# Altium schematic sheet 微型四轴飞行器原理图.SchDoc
size A4
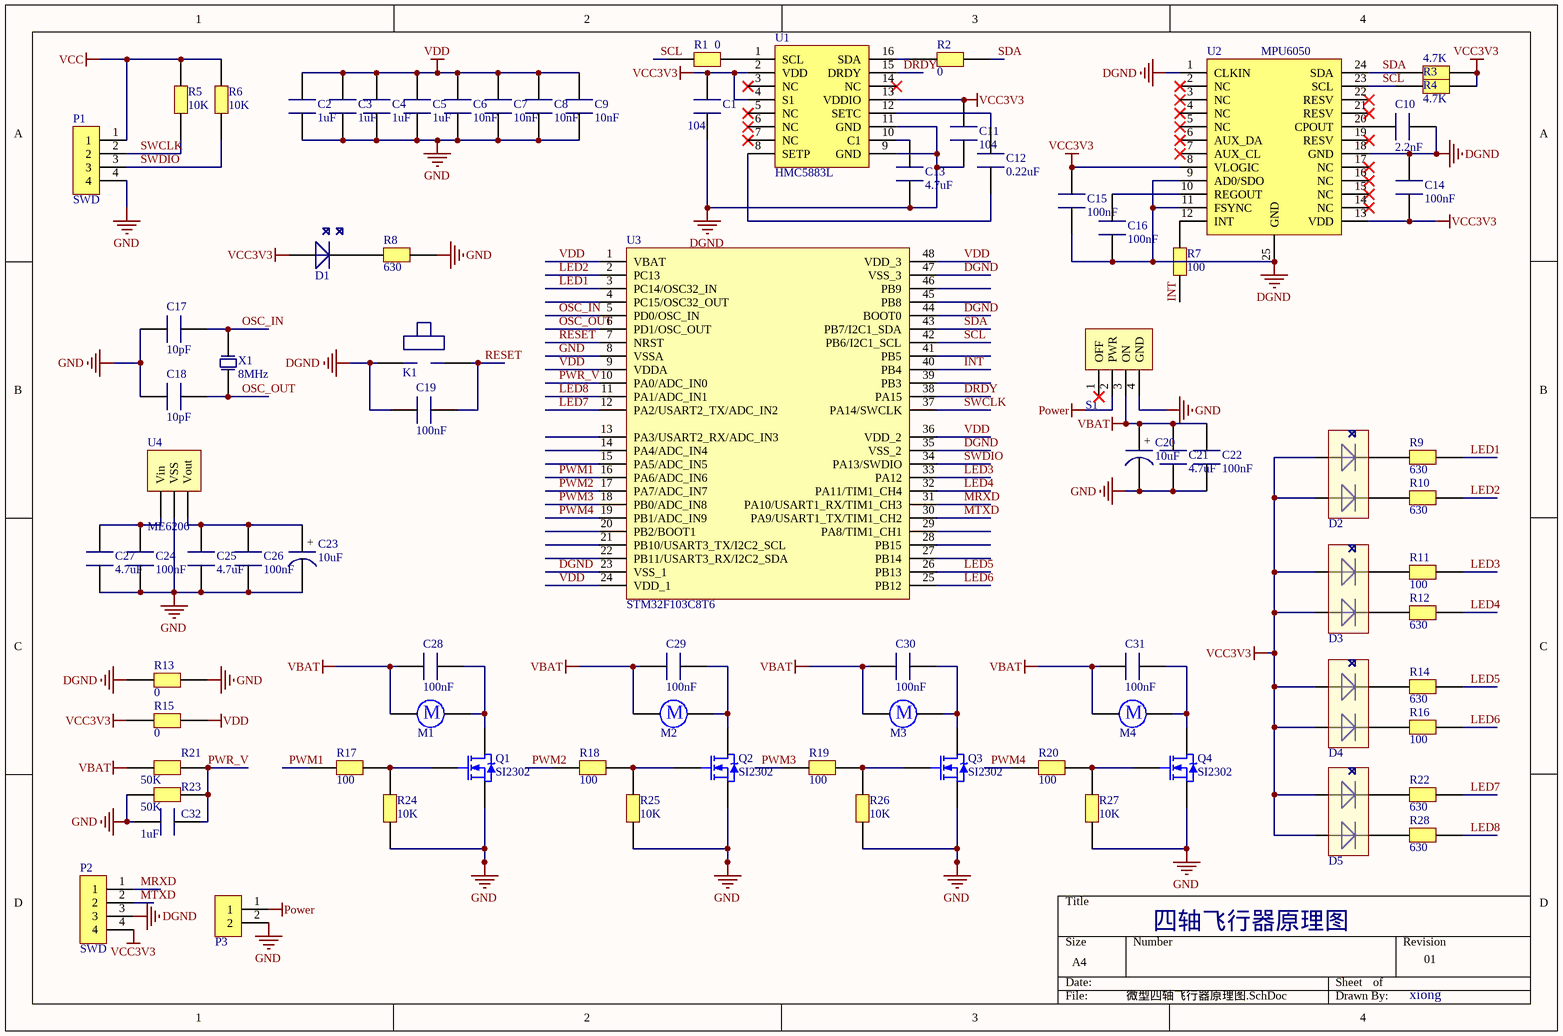
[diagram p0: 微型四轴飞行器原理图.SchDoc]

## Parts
C1  104  [C0603]
C2  ֵ: 1uF  [C0603]  (hidden comment: 104)
C3  ֵ: 1uF  [C0603]  (hidden comment: 104)
C4  ֵ: 1uF  [C0603]  (hidden comment: 104)
C5  ֵ: 1uF  [C0603]  (hidden comment: 104)
C6  ֵ: 10nF  [C0603]  (hidden comment: 104)
C7  ֵ: 10nF  [C0603]  (hidden comment: 104)
C8  ֵ: 10nF  [C0603]  (hidden comment: 104)
C9  ֵ: 10nF  [C0603]  (hidden comment: 104)
C10  ֵ: 2.2nF  [C0603]  (hidden comment: 104)
C11  104  [C0603]
C12  ֵ: 0.22uF  [C0603]  (hidden comment: 104)
C13  ֵ: 4.7uF  [C0603]  (hidden comment: 104)
C14  ֵ: 100nF  [C0603]  (hidden comment: 104)
C15  ֵ: 100nF  [C0603]  (hidden comment: 104)
C16  ֵ: 100nF  [C0603]  (hidden comment: 104)
C17  ֵ: 10pF  [C0603]  (hidden comment: 104)
C18  ֵ: 10pF  [C0603]  (hidden comment: 104)
C19  ֵ: 100nF  [C0603]  (hidden comment: 104)
C20  10uF  [TAJ-A1206]
C21  ֵ: 4.7uF  [C0603]  (hidden comment: 104)
C22  ֵ: 100nF  [C0603]  (hidden comment: 104)
C23  10uF  [TAJ-A1206]
C24  ֵ: 100nF  [C0603]  (hidden comment: 104)
C25  ֵ: 4.7uF  [C0603]  (hidden comment: 104)
C26  ֵ: 100nF  [C0603]  (hidden comment: 104)
C27  ֵ: 4.7uF  [C0603]  (hidden comment: 104)
C28  ֵ: 100nF  [C0603]  (hidden comment: 104)
C29  ֵ: 100nF  [C0603]  (hidden comment: 104)
C30  ֵ: 100nF  [C0603]  (hidden comment: 104)
C31  ֵ: 100nF  [C0603]  (hidden comment: 104)
C32  ֵ: 1uF  [C0603]  (hidden comment: 104)
D1  LED  [LED0805]  (value not drawn)
D2  LED2  [LED2]  (value not drawn)
D3  LED2  [LED2]  (value not drawn)
D4  LED2  [LED2]  (value not drawn)
D5  LED2  [LED2]  (value not drawn)
K1  KEY_SOP_2  [KEY_SOP2]  (value not drawn)
M1  Motor720  [Motor720]  (value not drawn)
M2  Motor720  [Motor720]  (value not drawn)
M3  Motor720  [Motor720]  (value not drawn)
M4  Motor720  [Motor720]  (value not drawn)
P1  下载接口: SWD  [PIN-4P]  (hidden comment: PIN-4P)
P2  下载接口: SWD  [PIN-4P]  (hidden comment: PIN-4P)
P3  PIN-2P  [PIN-2P]  (value not drawn)
Q1  SI2302  [SOT-23]
Q2  SI2302  [SOT-23]
Q3  SI2302  [SOT-23]
Q4  SI2302  [SOT-23]
R1  ֵ: 0  [R0603]  (hidden comment: 100)
R2  ֵ: 0  [R0603]  (hidden comment: 100)
R3  ֵ: 4.7K  [R0603]  (hidden comment: 100)
R4  ֵ: 4.7K  [R0603]  (hidden comment: 100)
R5  ֵ: 10K  [R0603]  (hidden comment: 100)
R6  ֵ: 10K  [R0603]  (hidden comment: 100)
R7  100  [R0603]
R8  ֵ: 630  [R0603]  (hidden comment: 100)
R9  ֵ: 630  [R0603]  (hidden comment: 100)
R10  ֵ: 630  [R0603]  (hidden comment: 100)
R11  100  [R0603]
R12  ֵ: 630  [R0603]  (hidden comment: 100)
R13  ֵ: 0  [R0603]  (hidden comment: 100)
R14  ֵ: 630  [R0603]  (hidden comment: 100)
R15  ֵ: 0  [R0603]  (hidden comment: 100)
R16  100  [R0603]
R17  100  [R0603]
R18  100  [R0603]
R19  100  [R0603]
R20  100  [R0603]
R21  50K  [R0603]
R22  ֵ: 630  [R0603]  (hidden comment: 100)
R23  ֵ: 50K  [R0603]  (hidden comment: 100)
R24  ֵ: 10K  [R0603]  (hidden comment: 100)
R25  ֵ: 10K  [R0603]  (hidden comment: 100)
R26  ֵ: 10K  [R0603]  (hidden comment: 100)
R27  ֵ: 10K  [R0603]  (hidden comment: 100)
R28  ֵ: 630  [R0603]  (hidden comment: 100)
S1  SwitchPin7  [SwitchPin7]  (value not drawn)
U1  HMC5883L  [HMC5883L-QFN]
U2  MPU6050  [MPU6050QFN]
U3  STM32F103C8T6  [LQFP48 7X7]
U4  ME6206  [sot-23]
X1  8MHz  [XTAL3_SOP]

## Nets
DGND: C1.1 C10.2 C11.2 C13.1 C14.2 C15.1 C16.1 C19.1 K1.1 P2.3 R13.1 U1.9(GND) U1.11(GND) U2.1(CLKIN) U2.9(AD0/SDO) U2.11(FSYNC) U2.18(GND) U2.25(GND) U3.23(VSS_1) U3.35(VSS_2) U3.44(BOOT0) U3.47(VSS_3)
GND: C2.1 C3.1 C4.1 C5.1 C6.1 C7.1 C8.1 C9.1 C17.1 C18.1 C20.2 C21.1 C22.1 C23.2 C24.1 C25.1 C26.1 C27.1 C32.2 P1.4 P3.2 Q1.2(S) Q2.2(S) Q3.2(S) Q4.2(S) R8.1 R13.2 R23.2 R24.1 R25.1 R26.1 R27.1 S1.4(GND) U3.8(VSSA) U4.1(VSS)
Power: P3.1 S1.2(PWR)
VBAT: C20.1 C21.2 C22.2 C28.1 C29.1 C30.1 C31.1 M1.1 M2.1 M3.1 M4.1 R21.2 S1.3(ON)
VCC: P1.1 R5.2 R6.2
VCC3V3: C1.2 C11.1 C14.1 C15.2 D1.1 D2.1 D2.2 D3.1 D3.2 D4.1 D4.2 D5.1 D5.2 P2.4 R3.1 R4.1 R15.1 U1.2(VDD) U1.4(S1) U1.13(VDDIO) U2.8(VLOGIC) U2.13(VDD)
VDD: C2.2 C3.2 C4.2 C5.2 C6.2 C7.2 C8.2 C9.2 R15.2 U3.1(VBAT) U3.9(VDDA) U3.24(VDD_1) U3.36(VDD_2) U3.48(VDD_3)
DRDY: U1.15(DRDY) U3.38(PA15)
INT: R7.1 U3.40(PB4)
LED1: R9.2 U3.3(PC14/OSC32_IN)
LED2: R10.2 U3.2(PC13)
LED3: R11.2 U3.33(PA12)
LED4: R12.2 U3.32(PA11/TIM1_CH4)
LED5: R14.2 U3.26(PB13)
LED6: R16.2 U3.25(PB12)
LED7: R22.2 U3.12(PA2/USART2_TX/ADC_IN2)
LED8: R28.2 U3.11(PA1/ADC_IN1)
MRXD: P2.1 U3.31(PA10/USART1_RX/TIM1_CH3)
MTXD: P2.2 U3.30(PA9/USART1_TX/TIM1_CH2)
OSC_IN: C17.2 U3.5(PD0/OSC_IN) X1.2
OSC_OUT: C18.2 U3.6(PD1/OSC_OUT) X1.1
PWM1: R17.2 U3.16(PA6/ADC_IN6)
PWM2: R18.2 U3.17(PA7/ADC_IN7)
PWM3: R19.2 U3.18(PB0/ADC_IN8)
PWM4: R20.2 U3.19(PB1/ADC_IN9)
PWR_V: C32.1 R21.1 R23.1 U3.10(PA0/ADC_IN0)
RESET: C19.2 K1.2 U3.7(NRST)
SCL: R1.1 R4.2 U2.23(SCL) U3.42(PB6/I2C1_SCL)
SDA: R2.2 R3.2 U2.24(SDA) U3.43(PB7/I2C1_SDA)
SWCLK: P1.2 R5.1 U3.37(PA14/SWCLK)
SWDIO: P1.3 R6.1 U3.34(PA13/SWDIO)
NetC10_1: C10.1 U2.20(CPOUT)
NetC12_1: C12.1 U1.8(SETP)
NetC12_2: C12.2 U1.12(SETC)
NetC13_2: C13.2 U1.10(C1)
NetC16_2: C16.2 U2.10(REGOUT)
NetC23_1: C23.1 C25.2 C26.2 U4.2(Vout)
NetC24_2: C24.2 C27.2 U4.3(Vin)
NetC28_2: C28.2 M1.2 Q1.3(D)
NetC29_2: C29.2 M2.2 Q2.3(D)
NetC30_2: C30.2 M3.2 Q3.3(D)
NetC31_2: C31.2 M4.2 Q4.3(D)
NetD1_2: D1.2 R8.2
NetD2_3: D2.3 R9.1
NetD2_4: D2.4 R10.1
NetD3_3: D3.3 R11.1
NetD3_4: D3.4 R12.1
NetD4_3: D4.3 R14.1
NetD4_4: D4.4 R16.1
NetD5_3: D5.3 R22.1
NetD5_4: D5.4 R28.1
NetQ1_1: Q1.1(G) R17.1 R24.2
NetQ2_1: Q2.1(G) R18.1 R25.2
NetQ3_1: Q3.1(G) R19.1 R26.2
NetQ4_1: Q4.1(G) R20.1 R27.2
NetR1_2: R1.2 U1.1(SCL)
NetR2_1: R2.1 U1.16(SDA)
NetR7_2: R7.2 U2.12(INT)

Not connected (* = marked no-connect by the designer): S1 1(OFF)*; U1 3(NC)* 5(NC)* 6(NC)* 7(NC)* 14(NC)*; U2 2(NC)* 3(NC)* 4(NC)* 5(NC)* 6(AUX_DA)* 7(AUX_CL)* 14(NC)* 15(NC)* 16(NC)* 17(NC)* 19(RESV)* 21(RESV)* 22(RESV)*; U3 4(PC15/OSC32_OUT) 13(PA3/USART2_RX/ADC_IN3) 14(PA4/ADC_IN4) 15(PA5/ADC_IN5) 20(PB2/BOOT1) 21(PB10/USART3_TX/I2C2_SCL) 22(PB11/USART3_RX/I2C2_SDA) 27(PB14) 28(PB15) 29(PA8/TIM1_CH1) 39(PB3) 41(PB5) 45(PB8) 46(PB9)

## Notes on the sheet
- 四轴飞行器原理图
- 01
- xiong

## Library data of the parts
C1-C19 C21 C22 C24-C32 = CAP0603: 0603
C20 C23 = CTAJ-A: TAJ-A
D1 = LED: 0805
D2-D5 = LED2: 0603
K1 = KEY_SOP2: KEY_SOP2_2*5
P1 P2 = PIN-4P: PIN-4P2.54; 封装: DIP4
P3 = PIN-2P: PIN-2P2.54
Q1-Q4 = SI2302: SOT-23
R1-R28 = RES0603: 0603
S1 = SwitchPin7: 贴片拨动开关; 封装: PasterPin7
U1 = HMC5883L: QFN
U2 = MPU6050: QFN
U3 = STM32F103-P48: STM32F103C8T6: LQPF-48
U4 = ME6206: SOT23
X1 = XTAL3: XTAL_SOP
